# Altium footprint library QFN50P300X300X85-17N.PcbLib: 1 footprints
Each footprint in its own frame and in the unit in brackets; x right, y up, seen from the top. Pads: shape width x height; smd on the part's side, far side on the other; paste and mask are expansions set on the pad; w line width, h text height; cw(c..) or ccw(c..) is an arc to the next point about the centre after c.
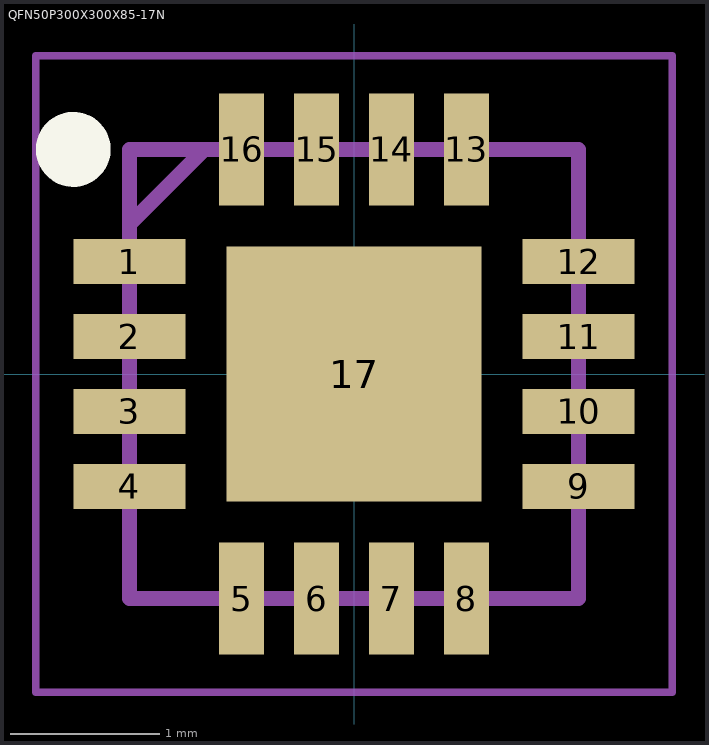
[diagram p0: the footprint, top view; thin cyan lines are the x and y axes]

## QFN50P300X300X85-17N [mm]
pads (17):
  rect 0.75x0.3 smd: 1(-1.5,0.75) 2(-1.5,0.25) 3(-1.5,-0.25) 4(-1.5,-0.75) 9(1.5,-0.75) 10(1.5,-0.25) 11(1.5,0.25) 12(1.5,0.75)
  rect 0.3x0.75 smd: 5(-0.75,-1.5) 6(-0.25,-1.5) 7(0.25,-1.5) 8(0.75,-1.5) 13(0.75,1.5) 14(0.25,1.5) 15(-0.25,1.5) 16(-0.75,1.5)
  rect 1.7x1.7 smd: 17(0,0)
Top Overlay:
  circle w0.25: c-1.875,1.5 r0.125
Mechanical 15:
  lines w0.1: -1.5,1 -1,1.5 ; -1.5,-1.5 1.5,-1.5 1.5,1.5 -1.5,1.5 -1.5,-1.5
Mechanical 20:
  lines w0.05: -2.125,-2.125 2.125,-2.125 2.125,2.125 -2.125,2.125 -2.125,-2.125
